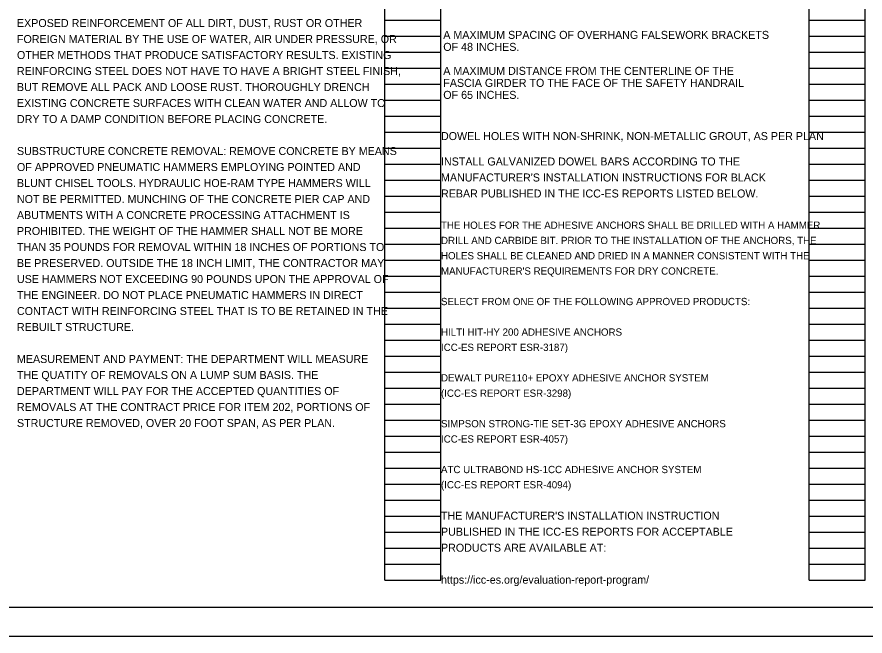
# Model space of a CAD drawing. Extents: x 0 to 48.4, y -19.4 to 22.
# Drawn here: x 9.82 to 24.66, y 0 to 10.83 of the extents above; entities that cross this region are included whole.
import ezdxf

# ---------------------------------------------------------------- set-up
doc = ezdxf.new("R2010")
doc.units = 0
for name, color, linetype in [('BR_P_Gen_Text', 7, 'Continuous'), ('SH_Border', 7, 'Continuous'), ('SH_Cut_Line', 7, 'Continuous'), ('SH_Data', 7, 'Continuous'), ('SH_Text', 7, 'Continuous')]:
    doc.layers.add(name, color=color, linetype=linetype)

msp = doc.modelspace()

# ---------------------------------------------------------------- linework, layer by layer
at = {"layer": 'SH_Border'}
msp.add_lwpolyline([(1.5, 21.5), (33.5, 21.5), (33.5, 0.5), (1.5, 0.5)], close=True, dxfattribs=at)
at = {"layer": 'SH_Cut_Line'}
msp.add_lwpolyline([(0, 0), (34, 0), (34, 22), (0, 22)], close=True, dxfattribs=at)
at = {"layer": 'SH_Data'}
for p, q in [((16.26, 0.98), (16.26, 21.14)), ((17.24, 0.98), (17.24, 21.14)), ((23.68, 0.98), (23.68, 21.14)), ((24.66, 0.98), (24.66, 21.14)), ((16.26, 10.78), (17.24, 10.78)), ((23.68, 10.78), (24.66, 10.78)), ((16.26, 10.5), (17.24, 10.5)), ((23.68, 10.5), (24.66, 10.5)), ((16.26, 10.22), (17.24, 10.22)), ((23.68, 10.22), (24.66, 10.22)), ((16.26, 9.94), (17.24, 9.94)), ((23.68, 9.94), (24.66, 9.94)), ((16.26, 9.66), (17.24, 9.66)), ((23.68, 9.66), (24.66, 9.66)), ((16.26, 9.38), (17.24, 9.38)), ((23.68, 9.38), (24.66, 9.38)), ((16.26, 9.1), (17.24, 9.1)), ((23.68, 9.1), (24.66, 9.1)), ((16.26, 8.82), (17.24, 8.82)), ((23.68, 8.82), (24.66, 8.82)), ((16.26, 8.54), (17.24, 8.54)), ((23.68, 8.54), (24.66, 8.54)), ((16.26, 8.26), (17.24, 8.26)), ((23.68, 8.26), (24.66, 8.26)), ((16.26, 7.98), (17.24, 7.98)), ((23.68, 7.98), (24.66, 7.98)), ((16.26, 7.7), (17.24, 7.7)), ((23.68, 7.7), (24.66, 7.7)), ((16.26, 7.42), (17.24, 7.42)), ((23.68, 7.42), (24.66, 7.42)), ((16.26, 7.14), (17.24, 7.14)), ((23.68, 7.14), (24.66, 7.14)), ((16.26, 6.86), (17.24, 6.86)), ((23.68, 6.86), (24.66, 6.86)), ((16.26, 6.58), (17.24, 6.58)), ((23.68, 6.58), (24.66, 6.58)), ((16.26, 6.3), (17.24, 6.3)), ((23.68, 6.3), (24.66, 6.3)), ((16.26, 6.02), (17.24, 6.02)), ((23.68, 6.02), (24.66, 6.02)), ((16.26, 5.74), (17.24, 5.74)), ((23.68, 5.74), (24.66, 5.74)), ((16.26, 5.46), (17.24, 5.46)), ((23.68, 5.46), (24.66, 5.46)), ((16.26, 5.18), (17.24, 5.18)), ((23.68, 5.18), (24.66, 5.18)), ((16.26, 4.9), (17.24, 4.9)), ((23.68, 4.9), (24.66, 4.9)), ((16.26, 4.62), (17.24, 4.62)), ((23.68, 4.62), (24.66, 4.62)), ((16.26, 4.34), (17.24, 4.34)), ((23.68, 4.34), (24.66, 4.34)), ((16.26, 4.06), (17.24, 4.06)), ((23.68, 4.06), (24.66, 4.06)), ((16.26, 3.78), (17.24, 3.78)), ((23.68, 3.78), (24.66, 3.78)), ((16.26, 3.5), (17.24, 3.5)), ((23.68, 3.5), (24.66, 3.5)), ((16.26, 3.22), (17.24, 3.22)), ((23.68, 3.22), (24.66, 3.22)), ((16.26, 2.94), (17.24, 2.94)), ((23.68, 2.94), (24.66, 2.94)), ((16.26, 2.66), (17.24, 2.66)), ((23.68, 2.66), (24.66, 2.66)), ((16.26, 2.38), (17.24, 2.38)), ((23.68, 2.38), (24.66, 2.38)), ((16.26, 2.1), (17.24, 2.1)), ((23.68, 2.1), (24.66, 2.1)), ((16.26, 1.82), (17.24, 1.82)), ((23.68, 1.82), (24.66, 1.82)), ((16.26, 1.54), (17.24, 1.54)), ((23.68, 1.54), (24.66, 1.54)), ((16.26, 1.26), (17.24, 1.26)), ((23.68, 1.26), (24.66, 1.26)), ((16.26, 0.98), (17.24, 0.98)), ((23.68, 0.98), (24.66, 0.98))]:
    msp.add_line(p, q, dxfattribs=at)

# ---------------------------------------------------------------- texts
at = {"layer": 'BR_P_Gen_Text'}
for s, height, p in [('EXPOSED REINFORCEMENT OF ALL DIRT, DUST, RUST OR OTHER ', 0.14, (9.82, 10.658)), ('FOREIGN MATERIAL BY THE USE OF WATER, AIR UNDER PRESSURE, OR ', 0.14, (9.82, 10.378)), ('OTHER METHODS THAT PRODUCE SATISFACTORY RESULTS. EXISTING ', 0.14, (9.82, 10.098)), ('REINFORCING STEEL DOES NOT HAVE TO HAVE A BRIGHT STEEL FINISH, ', 0.14, (9.82, 9.818)), ('BUT REMOVE ALL PACK AND LOOSE RUST. THOROUGHLY DRENCH ', 0.14, (9.82, 9.538)), ('EXISTING CONCRETE SURFACES WITH CLEAN WATER AND ALLOW TO ', 0.14, (9.82, 9.258)), ('DRY TO A DAMP CONDITION BEFORE PLACING CONCRETE. ', 0.14, (9.82, 8.978)), ('DOWEL HOLES WITH NON-SHRINK, NON-METALLIC GROUT, AS PER PLAN', 0.14, (17.24, 8.68)), ('SUBSTRUCTURE CONCRETE REMOVAL: REMOVE CONCRETE BY MEANS ', 0.14, (9.82, 8.418)), ('INSTALL GALVANIZED DOWEL BARS ACCORDING TO THE', 0.14, (17.24, 8.235)), ('OF APPROVED PNEUMATIC HAMMERS EMPLOYING POINTED AND ', 0.14, (9.82, 8.138)), ("MANUFACTURER'S INSTALLATION INSTRUCTIONS FOR BLACK", 0.14, (17.24, 7.955)), ('BLUNT CHISEL TOOLS. HYDRAULIC HOE-RAM TYPE HAMMERS WILL ', 0.14, (9.82, 7.858)), ('NOT BE PERMITTED. MUNCHING OF THE CONCRETE PIER CAP AND ', 0.14, (9.82, 7.578)), ('REBAR PUBLISHED IN THE ICC-ES REPORTS LISTED BELOW.', 0.14, (17.24, 7.675)), ('ABUTMENTS WITH A CONCRETE PROCESSING ATTACHMENT IS ', 0.14, (9.82, 7.298)), ('PROHIBITED. THE WEIGHT OF THE HAMMER SHALL NOT BE MORE ', 0.14, (9.82, 7.018)), ('THE HOLES FOR THE ADHESIVE ANCHORS SHALL BE DRILLED WITH A HAMMER ', 0.12727, (17.24, 7.127)), ('DRILL AND CARBIDE BIT. PRIOR TO THE INSTALLATION OF THE ANCHORS, THE ', 0.12727, (17.24, 6.86)), ('THAN 35 POUNDS FOR REMOVAL WITHIN 18 INCHES OF PORTIONS TO ', 0.14, (9.82, 6.738)), ('HOLES SHALL BE CLEANED AND DRIED IN A MANNER CONSISTENT WITH THE ', 0.12727, (17.24, 6.593)), ('BE PRESERVED. OUTSIDE THE 18 INCH LIMIT, THE CONTRACTOR MAY ', 0.14, (9.82, 6.458)), ("MANUFACTURER'S REQUIREMENTS FOR DRY CONCRETE.", 0.12727, (17.24, 6.325)), ('USE HAMMERS NOT EXCEEDING 90 POUNDS UPON THE APPROVAL OF ', 0.14, (9.82, 6.178)), ('THE ENGINEER. DO NOT PLACE PNEUMATIC HAMMERS IN DIRECT ', 0.14, (9.82, 5.898)), ('SELECT FROM ONE OF THE FOLLOWING APPROVED PRODUCTS:', 0.12727, (17.24, 5.791)), ('CONTACT WITH REINFORCING STEEL THAT IS TO BE RETAINED IN THE ', 0.14, (9.82, 5.618)), ('REBUILT STRUCTURE. ', 0.14, (9.82, 5.338)), ('HILTI HIT-HY 200 ADHESIVE ANCHORS', 0.12727, (17.24, 5.256)), ('ICC-ES REPORT ESR-3187)', 0.12727, (17.24, 4.989)), ('MEASUREMENT AND PAYMENT: THE DEPARTMENT WILL MEASURE ', 0.14, (9.82, 4.778)), ('THE QUATITY OF REMOVALS ON A LUMP SUM BASIS. THE ', 0.14, (9.82, 4.498)), ('DEWALT PURE110+ EPOXY ADHESIVE ANCHOR SYSTEM', 0.12727, (17.24, 4.455)), ('DEPARTMENT WILL PAY FOR THE ACCEPTED QUANTITIES OF ', 0.14, (9.82, 4.218)), ('(ICC-ES REPORT ESR-3298)', 0.12727, (17.24, 4.187)), ('REMOVALS AT THE CONTRACT PRICE FOR ITEM 202, PORTIONS OF ', 0.14, (9.82, 3.938)), ('STRUCTURE REMOVED, OVER 20 FOOT SPAN, AS PER PLAN.', 0.14, (9.82, 3.658)), ('SIMPSON STRONG-TIE SET-3G EPOXY ADHESIVE ANCHORS', 0.12727, (17.24, 3.653)), ('ICC-ES REPORT ESR-4057)', 0.12727, (17.24, 3.385)), ('ATC ULTRABOND HS-1CC ADHESIVE ANCHOR SYSTEM', 0.12727, (17.24, 2.851)), ('(ICC-ES REPORT ESR-4094)', 0.12727, (17.24, 2.584)), ("THE MANUFACTURER'S INSTALLATION INSTRUCTION", 0.14, (17.24, 2.036)), ('PUBLISHED IN THE ICC-ES REPORTS FOR ACCEPTABLE', 0.14, (17.24, 1.756)), ('PRODUCTS ARE AVAILABLE AT:', 0.14, (17.24, 1.476)), ('https://icc-es.org/evaluation-report-program/', 0.14, (17.24, 0.916))]:
    msp.add_text(s, height=height, dxfattribs=at).set_placement(p)
at = {"layer": 'SH_Text'}
for s, p in [('A MAXIMUM SPACING OF OVERHANG FALSEWORK BRACKETS', (17.28, 10.451)), ('OF 48 INCHES.', (17.28, 10.241)), ('A MAXIMUM DISTANCE FROM THE CENTERLINE OF THE', (17.28, 9.821)), ('FASCIA GIRDER TO THE FACE OF THE SAFETY HANDRAIL', (17.28, 9.611)), ('OF 65 INCHES.', (17.28, 9.401))]:
    msp.add_text(s, height=0.14, dxfattribs=at).set_placement(p)

doc.saveas('drawing.dxf')
